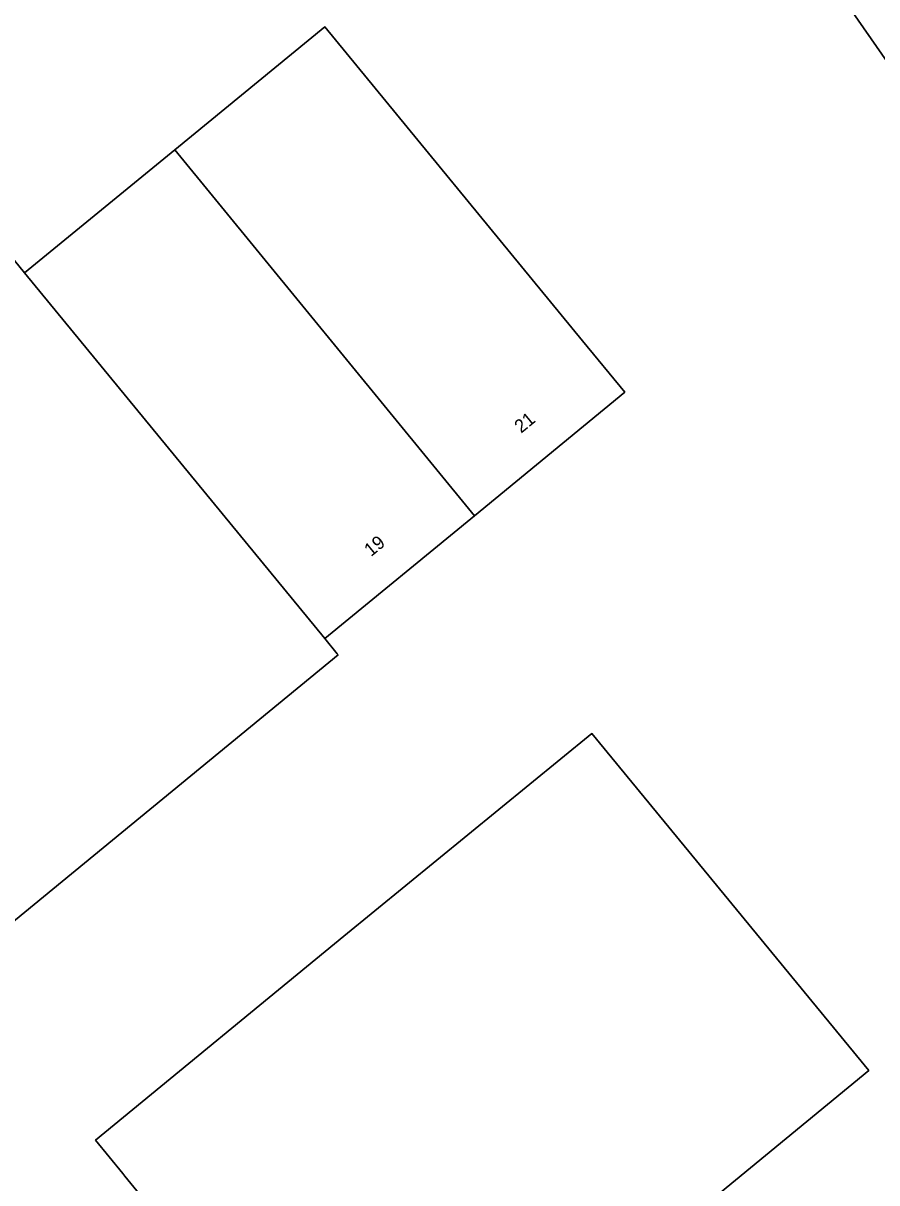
# Model space of a CAD drawing. Extents: x 156702 to 158052, y 387630 to 388992.
# Drawn here: x 157235.7 to 157299.9, y 387836.4 to 387923.6 of the extents above; entities that cross this region are included whole.
import ezdxf

# ---------------------------------------------------------------- set-up
doc = ezdxf.new("R2010")
doc.units = 0
for name, color, linetype in [('IMGEO_Erf', 7, 'Continuous'), ('IMGEO_Pand', 7, 'Continuous'), ('IMGEO_Pand_nummerreeks', 7, 'Continuous')]:
    doc.layers.add(name, color=color, linetype=linetype)

msp = doc.modelspace()

# ---------------------------------------------------------------- linework, layer by layer
at = {"layer": 'IMGEO_Erf'}
msp.add_lwpolyline([(157328.033, 387933.28), (157335.557, 387922.605), (157314.148, 387907.716), (157312.379, 387909.37), (157309.858, 387907.487), (157262.615, 387975.435)], dxfattribs=at)
for points in [[(157277.793, 387899.706), (157280.965, 387895.842), (157269.653, 387886.542), (157258.413, 387877.301), (157259.351, 387876.158), (157259.415, 387876.08), (157231.347, 387853.023), (157224.82, 387860.984), (157224.742, 387861.079), (157211.242, 387877.546), (157204.726, 387885.494), (157208.589, 387888.669), (157232.772, 387908.543), (157235.822, 387904.802), (157247.12, 387914.055), (157258.419, 387923.308)], [(157278.484, 387870.163), (157299.316, 387844.802), (157291.542, 387838.402), (157280.697, 387829.474), (157285.889, 387823.145), (157279.697, 387818.085), (157284.76, 387811.91), (157273.737, 387802.823), (157270.622, 387800.255), (157272.057, 387798.475), (157266.039, 387793.519), (157255.901, 387805.842), (157261.926, 387810.809), (157262.25, 387810.377), (157263.979, 387811.778), (157249.792, 387829.047), (157249.636, 387829.236), (157246.596, 387832.937), (157246.438, 387833.129), (157243.382, 387836.849), (157243.219, 387837.048), (157241.16, 387839.554), (157259.836, 387854.902)]]:
    msp.add_lwpolyline(points, close=True, dxfattribs=at)
at = {"layer": 'IMGEO_Pand'}
for points in [[(157309.365, 387976.369), (157306.145, 387981), (157292.934, 388000), (157260.917, 387977.877), (157262.615, 387975.435), (157309.858, 387907.487), (157312.379, 387909.37), (157314.148, 387907.716), (157335.557, 387922.605), (157328.033, 387933.28), (157335.643, 387938.575), (157332.788, 387942.681)], [(157247.12, 387914.055), (157269.653, 387886.542), (157280.965, 387895.842), (157277.793, 387899.706), (157258.419, 387923.308)], [(157247.12, 387914.055), (157235.822, 387904.802), (157258.413, 387877.301), (157269.653, 387886.542)], [(157235.822, 387904.802), (157232.772, 387908.543), (157208.589, 387888.669), (157204.726, 387885.494), (157211.242, 387877.546), (157224.742, 387861.079), (157224.82, 387860.984), (157231.347, 387853.023), (157259.415, 387876.08), (157259.351, 387876.158), (157258.413, 387877.301)], [(157249.792, 387829.047), (157263.979, 387811.778), (157262.25, 387810.377), (157261.926, 387810.809), (157255.901, 387805.842), (157266.039, 387793.519), (157272.057, 387798.475), (157270.622, 387800.255), (157273.737, 387802.823), (157284.76, 387811.91), (157279.697, 387818.085), (157285.889, 387823.145), (157280.697, 387829.474), (157291.542, 387838.402), (157299.316, 387844.802), (157278.484, 387870.163), (157259.836, 387854.902), (157241.16, 387839.554), (157243.219, 387837.048), (157243.382, 387836.849), (157246.438, 387833.129), (157246.596, 387832.937), (157249.636, 387829.236)]]:
    msp.add_lwpolyline(points, close=True, dxfattribs=at)

# ---------------------------------------------------------------- texts
at = {"layer": 'IMGEO_Pand_nummerreeks'}
for s, p in [('21', (157273.175, 387892.701)), ('19', (157261.882, 387883.416))]:
    msp.add_text(s, height=1, rotation=39.42523, dxfattribs=at).set_placement(p)

doc.saveas('drawing.dxf')
